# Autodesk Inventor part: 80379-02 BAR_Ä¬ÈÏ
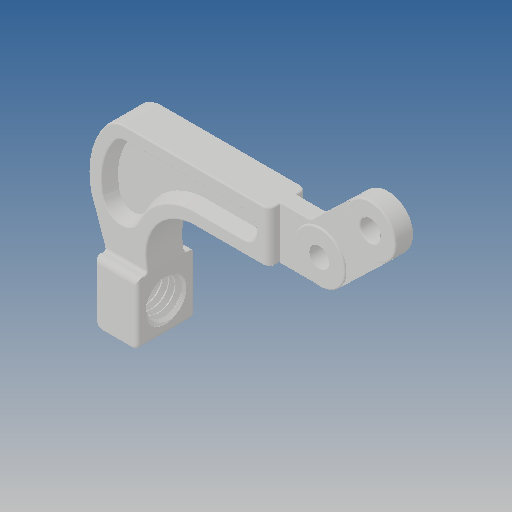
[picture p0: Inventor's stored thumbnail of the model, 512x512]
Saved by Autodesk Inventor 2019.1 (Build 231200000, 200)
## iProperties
Created: 2010-06
Part Number: 80379-02 BAR_Ä¬ÈÏ
Material: Ogólny
Document SubType Name: Modeling
Designer: CADENGINEERING4
Density: 1 g/cm^3
Appearance: Domyślna
Author: CADENGINEERING4
Revision Number: ÈÎºÎ
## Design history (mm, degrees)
feature "NONE"
node "Bryła1"
